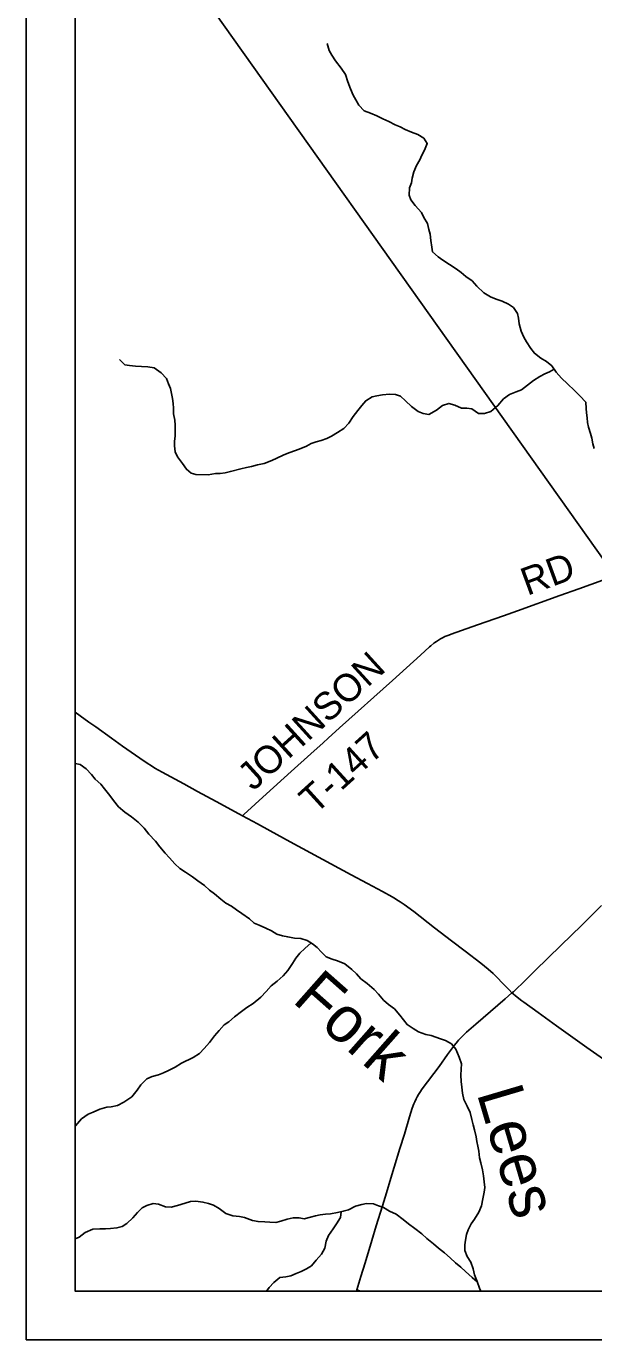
# Model space of a CAD drawing. Extents: x 0 to 34, y 0 to 22.
# Drawn here: x 2 to 3.164, y 14 to 16.697 of the extents above; entities that cross this region are included whole.
import ezdxf

# ---------------------------------------------------------------- set-up
doc = ezdxf.new("R2010")
doc.units = 0
for name, color, linetype in [('Default', 7, 'Continuous'), ('GM_X_County_Road', 7, 'Continuous'), ('GM_X_Minor_River', 7, 'Continuous'), ('GM_X_Minor_River_Text', 7, 'Continuous'), ('GM_X_Township_Road', 7, 'Continuous'), ('GM_X_Township_Road_Text', 7, 'Continuous'), ('SH_Cut_Line', 7, 'Continuous'), ('SH_Data', 7, 'Continuous')]:
    doc.layers.add(name, color=color, linetype=linetype)

msp = doc.modelspace()

# ---------------------------------------------------------------- linework, layer by layer
at = {"layer": 'Default'}
msp.add_lwpolyline([(6.6858, 19.0362), (6.6949, 19.1537), (6.8302, 20.9), (3.1229, 20.9), (2.9275, 20.8467), (2.2946, 20.6707), (2.1, 20.6202), (2.1, 17.1279), (2.1211, 17.1003), (3.2076, 15.5689), (3.4902, 15.1704), (4.0558, 14.3671), (4.1658, 14.2105), (4.302, 14.3105), (5.6165, 15.2674), (6.0871, 15.6176), (6.2834, 15.7529), (6.4392, 15.8657), (6.5428, 17.1931), (6.5451, 17.2211), (6.6309, 18.3364), (6.6363, 18.3979), (6.6654, 18.7733)], dxfattribs=at)
msp.add_lwpolyline([(2.1, 17.1279), (2.1, 14.1), (4.022, 14.1), (4.1658, 14.2105), (4.0558, 14.3671), (3.4902, 15.1704), (3.2076, 15.5689), (2.1211, 17.1003)], close=True, dxfattribs=at)
at = {"layer": 'GM_X_County_Road'}
msp.add_line((2.6773, 14.1), (2.678, 14.1023), dxfattribs=at)
for points in [[(2.4436, 15.0755), (2.4361, 15.0796), (2.3897, 15.1048), (2.3515, 15.1255), (2.3232, 15.141), (2.279, 15.1651), (2.264, 15.1738), (2.2569, 15.178), (2.248, 15.1835), (2.2327, 15.194), (2.2153, 15.2061), (2.1971, 15.2189), (2.1749, 15.2349), (2.1426, 15.2582), (2.1284, 15.2682), (2.1107, 15.2808), (2.1, 15.2885)], [(2.9966, 14.712), (2.9905, 14.7181), (2.9778, 14.7317), (2.9658, 14.7444), (2.9578, 14.7522), (2.948, 14.7609), (2.933, 14.773), (2.9004, 14.7979), (2.8728, 14.8191), (2.8378, 14.8459), (2.7951, 14.8791), (2.7756, 14.8935), (2.7673, 14.8991), (2.7637, 14.9014), (2.7541, 14.9072), (2.7506, 14.9092), (2.7306, 14.9201), (2.7, 14.9366), (2.6666, 14.9547), (2.5835, 14.9995), (2.5416, 15.0225), (2.5006, 15.0447), (2.4744, 15.0589), (2.4436, 15.0755)], [(2.9966, 14.712), (2.9997, 14.7146), (3.0009, 14.7156), (3.003, 14.7176), (3.0051, 14.7195), (3.0196, 14.7336), (3.0437, 14.7571), (3.0976, 14.8098), (3.1393, 14.8507), (3.1805, 14.8912)], [(2.678, 14.1023), (2.6864, 14.1299), (2.695, 14.1579), (2.7089, 14.2036), (2.7181, 14.234), (2.7307, 14.2749), (2.7388, 14.3017), (2.748, 14.3314), (2.7551, 14.3545), (2.7667, 14.3926), (2.7758, 14.4223), (2.7864, 14.4574), (2.792, 14.4751), (2.7955, 14.4843), (2.7971, 14.4882), (2.7999, 14.4944), (2.802, 14.4986), (2.8049, 14.5035), (2.8075, 14.5077), (2.8124, 14.5151), (2.847, 14.5613), (2.8646, 14.5855), (2.8785, 14.6045), (2.8848, 14.6124), (2.887, 14.615), (2.8913, 14.6197), (2.8948, 14.6232), (2.9002, 14.6284), (2.9033, 14.6312), (2.9224, 14.648), (2.9824, 14.6998), (2.9966, 14.712)], [(3.1841, 14.576), (3.1503, 14.6003), (3.1214, 14.6207), (3.0881, 14.6447), (3.0502, 14.6718), (3.0206, 14.6931), (3.0171, 14.6958), (3.0074, 14.7032), (3.0033, 14.7065), (2.9966, 14.712)]]:
    msp.add_lwpolyline(points, dxfattribs=at)
at = {"layer": 'GM_X_Minor_River'}
for points in [[(3.1655, 15.83), (3.1622, 15.8395), (3.1605, 15.8513), (3.1575, 15.8608), (3.1535, 15.8734), (3.1517, 15.8833), (3.1507, 15.8928), (3.1497, 15.9027), (3.149, 15.9122), (3.148, 15.9251), (3.1356, 15.9382), (3.1247, 15.9486), (3.1104, 15.9624), (3.0984, 15.9743), (3.0875, 15.9862), (3.0786, 15.9992), (3.0676, 16.0081), (3.0555, 16.0154), (3.0427, 16.0255), (3.0352, 16.035), (3.0267, 16.0488), (3.0211, 16.0584), (3.0151, 16.071), (3.0115, 16.0855), (3.0101, 16.0972), (3.0079, 16.1068), (2.9994, 16.1194), (2.9895, 16.126), (2.9767, 16.1326), (2.9638, 16.1361), (2.9528, 16.1412), (2.9388, 16.1497), (2.9246, 16.1632), (2.9148, 16.1739), (2.902, 16.1832), (2.8922, 16.1913), (2.8824, 16.199), (2.8684, 16.2075), (2.8548, 16.2164), (2.845, 16.2233), (2.8337, 16.2333), (2.8319, 16.2429), (2.8298, 16.2566), (2.8288, 16.2699), (2.8263, 16.2794), (2.823, 16.2916), (2.8159, 16.3042), (2.8107, 16.3145), (2.7976, 16.3287), (2.789, 16.3402), (2.7853, 16.3501), (2.7862, 16.3653), (2.7902, 16.3755), (2.7918, 16.385), (2.795, 16.3975), (2.8005, 16.4108), (2.8075, 16.4225), (2.8118, 16.4323), (2.8172, 16.4421), (2.8227, 16.4557), (2.8156, 16.4668), (2.8031, 16.4742), (2.7907, 16.4792), (2.7774, 16.4847), (2.7672, 16.4905), (2.757, 16.4944), (2.7441, 16.501), (2.7316, 16.5069), (2.7192, 16.5131), (2.7063, 16.5186), (2.693, 16.5229), (2.6825, 16.5344), (2.6762, 16.5455), (2.671, 16.5554), (2.6654, 16.5684), (2.6599, 16.5829), (2.6551, 16.5974), (2.6458, 16.6104), (2.6342, 16.6254), (2.6267, 16.6376), (2.6215, 16.6472), (2.6171, 16.6616)], [(3.0829, 15.9929), (3.0735, 15.9875), (3.0639, 15.9831), (3.0539, 15.9778), (3.0409, 15.9696), (3.0286, 15.9595), (3.0159, 15.9502), (3.0052, 15.9461), (2.9915, 15.9409), (2.9792, 15.9316), (2.9676, 15.918), (2.9534, 15.906), (2.94, 15.902), (2.9282, 15.9018), (2.9143, 15.9114), (2.904, 15.9127), (2.893, 15.9124), (2.879, 15.919), (2.8672, 15.9222), (2.8542, 15.9182), (2.842, 15.9084), (2.8262, 15.8999), (2.8145, 15.9015), (2.8039, 15.9055), (2.7907, 15.9159), (2.7783, 15.9278), (2.7681, 15.937), (2.7575, 15.9405), (2.7453, 15.9411), (2.7309, 15.9397), (2.7194, 15.9379), (2.7099, 15.9358), (2.6965, 15.9279), (2.6887, 15.9181), (2.6806, 15.9076), (2.6706, 15.8952), (2.662, 15.8816), (2.6516, 15.8711), (2.6386, 15.8625), (2.626, 15.8554), (2.6164, 15.8502), (2.6049, 15.8462), (2.5946, 15.8436), (2.5843, 15.8399), (2.5747, 15.8347), (2.5633, 15.8299), (2.5522, 15.8259), (2.5388, 15.8211), (2.5273, 15.8163), (2.5143, 15.8099), (2.5036, 15.8051), (2.4879, 15.7992), (2.4742, 15.796), (2.462, 15.7927), (2.4517, 15.7905), (2.4403, 15.788), (2.4189, 15.7829), (2.4082, 15.78), (2.3979, 15.7786), (2.3884, 15.7783), (2.3735, 15.7758), (2.348, 15.7761), (2.3382, 15.7793), (2.3284, 15.7873), (2.3205, 15.7988), (2.31, 15.8126), (2.3056, 15.8233), (2.3042, 15.8351), (2.3044, 15.845), (2.3056, 15.8552), (2.3058, 15.8674), (2.3055, 15.878), (2.3045, 15.8879), (2.3024, 15.9008), (2.3021, 15.9126), (2.3015, 15.9225), (2.2997, 15.9328), (2.2979, 15.9427), (2.2958, 15.9533), (2.2921, 15.9629), (2.2876, 15.9736), (2.2768, 15.9855), (2.2624, 15.9951), (2.2491, 15.9976), (2.2362, 15.9985), (2.224, 15.999), (2.2115, 16.0003), (2.202, 16.0019), (2.1911, 16.0126)], [(2.8949, 14.5059), (2.8935, 14.5188), (2.8921, 14.5299), (2.8918, 14.5431), (2.8923, 14.5557), (2.8932, 14.5667), (2.8884, 14.5804), (2.8813, 14.5964), (2.8723, 14.6078), (2.8599, 14.6144), (2.85, 14.6179), (2.8311, 14.6245), (2.8198, 14.6269), (2.8046, 14.6324), (2.7941, 14.6393), (2.7812, 14.647), (2.7741, 14.6566), (2.7662, 14.6661), (2.7553, 14.6791), (2.7433, 14.688), (2.7331, 14.6972), (2.723, 14.7098), (2.714, 14.7194), (2.6997, 14.7312), (2.6865, 14.7409), (2.6775, 14.7512), (2.6677, 14.7604), (2.6534, 14.7715), (2.6386, 14.7777), (2.6277, 14.7816), (2.6156, 14.7863), (2.6058, 14.7959), (2.5971, 14.8054), (2.587, 14.8131), (2.576, 14.8197), (2.5635, 14.8236), (2.5506, 14.8245), (2.5366, 14.8269), (2.5256, 14.8292), (2.5143, 14.8324), (2.503, 14.8397), (2.4916, 14.8451), (2.4777, 14.8509), (2.4678, 14.8552), (2.458, 14.8644), (2.4422, 14.8752), (2.4313, 14.8825), (2.4211, 14.8901), (2.4094, 14.8963), (2.3992, 14.9048), (2.386, 14.9155), (2.3762, 14.9232), (2.3657, 14.9328), (2.3521, 14.942), (2.3408, 14.9505), (2.3269, 14.9601), (2.3148, 14.9674), (2.3046, 14.9774), (2.2937, 14.9892), (2.2851, 14.9988), (2.2742, 15.0118), (2.2648, 15.0236), (2.2513, 15.0382), (2.2416, 15.05), (2.2295, 15.0623), (2.2156, 15.0734), (2.2024, 15.083), (2.1892, 15.0942), (2.1787, 15.1072), (2.1716, 15.1175), (2.1603, 15.1309), (2.1528, 15.1404), (2.1415, 15.1508), (2.1337, 15.1603), (2.1231, 15.1722), (2.1103, 15.1807), (2.1, 15.1832)], [(2.5845, 14.8146), (2.5717, 14.8034), (2.561, 14.7936), (2.5529, 14.7834), (2.546, 14.7725), (2.5368, 14.7582), (2.5272, 14.7469), (2.5145, 14.7363), (2.5027, 14.7266), (2.492, 14.7149), (2.4812, 14.7036), (2.4652, 14.6905), (2.4522, 14.6823), (2.4415, 14.6736), (2.427, 14.6631), (2.4155, 14.653), (2.406, 14.6466), (2.3956, 14.6349), (2.3864, 14.624), (2.3757, 14.6105), (2.3653, 14.598), (2.3554, 14.5879), (2.3424, 14.5796), (2.3187, 14.5677), (2.3058, 14.5599), (2.292, 14.5528), (2.2814, 14.5479), (2.2711, 14.5438), (2.2582, 14.5405), (2.2475, 14.5357), (2.2352, 14.5233), (2.2276, 14.5127), (2.2168, 14.4988), (2.2, 14.4876), (2.1874, 14.4808), (2.1745, 14.4783), (2.165, 14.4772), (2.1506, 14.4732), (2.1372, 14.4669), (2.1273, 14.4628), (2.1132, 14.4534), (2.1009, 14.4391), (2.1, 14.4381)], [(2.9327, 14.1), (2.93, 14.1059), (2.9252, 14.1193), (2.9196, 14.133), (2.9167, 14.1459), (2.9119, 14.1592), (2.9048, 14.1707), (2.8999, 14.1829), (2.8997, 14.1947), (2.9013, 14.2045), (2.9033, 14.2159), (2.9064, 14.2257), (2.9126, 14.2378), (2.9199, 14.2476), (2.9287, 14.2616), (2.9338, 14.2748), (2.937, 14.2896), (2.9397, 14.3028), (2.9406, 14.3127), (2.9392, 14.3241), (2.9381, 14.3363), (2.936, 14.3488), (2.9327, 14.3632), (2.9301, 14.3735), (2.9284, 14.3872), (2.9262, 14.3975), (2.9244, 14.407), (2.9233, 14.4169), (2.9197, 14.4309), (2.9171, 14.4412), (2.9145, 14.4522), (2.9105, 14.4667), (2.9049, 14.4796), (2.8978, 14.4934), (2.8949, 14.5059)], [(2.9252, 14.1191), (2.9146, 14.1277), (2.9015, 14.14), (2.8913, 14.1488), (2.8807, 14.1576), (2.8698, 14.168), (2.8582, 14.1783), (2.8461, 14.1883), (2.8356, 14.1971), (2.822, 14.2079), (2.8115, 14.2171), (2.7975, 14.2286), (2.7843, 14.2378), (2.773, 14.247), (2.7591, 14.2578), (2.7455, 14.264), (2.7327, 14.2713), (2.7228, 14.2752), (2.7122, 14.2787), (2.6982, 14.2796), (2.6883, 14.2778), (2.6754, 14.2741), (2.6613, 14.267), (2.6503, 14.2637), (2.6385, 14.2612), (2.624, 14.2586), (2.6142, 14.2576), (2.6028, 14.2562), (2.5933, 14.2544), (2.583, 14.2518), (2.5701, 14.2485), (2.5602, 14.2501), (2.5473, 14.2502), (2.5355, 14.2473), (2.5222, 14.2432), (2.5119, 14.2407), (2.4994, 14.2412), (2.4892, 14.2424), (2.4755, 14.2425), (2.4642, 14.2449), (2.4479, 14.2507), (2.4373, 14.2531), (2.4236, 14.2544), (2.4097, 14.2594), (2.3957, 14.2691), (2.384, 14.2764), (2.3738, 14.2795), (2.3624, 14.2826), (2.348, 14.2847), (2.337, 14.2836), (2.326, 14.2803), (2.3104, 14.2759), (2.2975, 14.2719), (2.2857, 14.2727), (2.271, 14.2782), (2.2603, 14.2794), (2.2474, 14.2753), (2.2375, 14.2705), (2.2279, 14.2615), (2.2187, 14.2505), (2.2065, 14.2385), (2.1965, 14.2325), (2.1859, 14.2296), (2.173, 14.2286), (2.1627, 14.2279), (2.151, 14.2276), (2.1365, 14.227), (2.1209, 14.2199), (2.1083, 14.2109), (2.1, 14.2074)], [(2.6463, 14.2629), (2.6448, 14.2512), (2.6364, 14.238), (2.6298, 14.2278), (2.6198, 14.2143), (2.6155, 14.2025), (2.6124, 14.1878), (2.6058, 14.1757), (2.5951, 14.1633), (2.5855, 14.152), (2.5752, 14.1456), (2.5638, 14.1404), (2.5539, 14.1359), (2.5428, 14.1311), (2.5325, 14.1289), (2.52, 14.1279), (2.5082, 14.1174), (2.4986, 14.1072), (2.4932, 14.1)]]:
    msp.add_lwpolyline(points, dxfattribs=at)
at = {"layer": 'GM_X_Township_Road'}
for points in [[(2.4436, 15.0755), (2.4464, 15.0781), (2.4929, 15.1208), (2.5436, 15.1667), (2.5838, 15.2028), (2.6091, 15.2257), (2.6193, 15.2349), (2.6428, 15.2561), (2.7512, 15.3538), (2.8089, 15.4058), (2.8272, 15.4224), (2.8299, 15.4247), (2.8365, 15.4302), (2.8384, 15.4316), (2.8414, 15.4338), (2.8436, 15.4352), (2.8476, 15.4378), (2.8502, 15.4392), (2.8557, 15.442), (2.859, 15.4435), (2.8669, 15.4467), (2.8717, 15.4484), (2.8928, 15.4559), (2.9258, 15.4678), (2.9793, 15.4862), (3.0079, 15.4965), (3.095, 15.528), (3.1336, 15.5419), (3.2078, 15.5684)], [(2.678, 14.1023), (2.684, 14.1001), (2.6842, 14.1)]]:
    msp.add_lwpolyline(points, dxfattribs=at)
at = {"layer": 'SH_Cut_Line'}
msp.add_lwpolyline([(6.6858, 19.0362), (6.6949, 19.1537), (6.8302, 20.9), (2.1, 20.9), (2.1, 14.1), (4.022, 14.1), (4.1658, 14.2105), (4.302, 14.3105), (5.6165, 15.2674), (6.0871, 15.6176), (6.2834, 15.7529), (6.4392, 15.8657), (6.5428, 17.1931), (6.5451, 17.2211), (6.6309, 18.3364), (6.6363, 18.3979), (6.6654, 18.7733)], dxfattribs=at)
at = {"layer": 'SH_Data'}
for p, q in [((2, 21), (2, 14)), ((2.1, 20.9), (2.1, 14.1)), ((2.1, 14.1), (8.9, 14.1)), ((2.1, 14.1), (2.1, 14.1)), ((2, 14), (9, 14))]:
    msp.add_line(p, q, dxfattribs=at)

# ---------------------------------------------------------------- texts
at = {"layer": 'GM_X_Minor_River_Text'}
for s, height, rotation, p in [('Fork', 0.09469, 318.5238, (2.5435, 14.6949)), ('Lees', 0.0947, 286.5051, (2.9239, 14.5063))]:
    msp.add_text(s, height=height, rotation=rotation, dxfattribs=at).set_placement(p)
at = {"layer": 'GM_X_Township_Road_Text'}
for s, rotation, p in [('RD', 20.1502, (3.0279, 15.5271)), ('JOHNSON', 42.2435, (2.4656, 15.1251)), ('T-147', 42.237, (2.5927, 15.0772))]:
    msp.add_text(s, height=0.05682, rotation=rotation, dxfattribs=at).set_placement(p)

doc.saveas('drawing.dxf')
